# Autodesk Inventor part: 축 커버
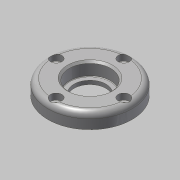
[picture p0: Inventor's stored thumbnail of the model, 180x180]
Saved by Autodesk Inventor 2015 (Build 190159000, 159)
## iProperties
Created: 2015-10
Part Number: 축 커버
Document SubType Name: Modeling
Designer: mdu
Density: 7.86 g/cm^3
Material: 강철, 연강
Mass: 76.1259 g
Surface Area: 48.0703 cm^2
Volume: 9.68523 cm^3
Appearance: Steel
Author: mdu
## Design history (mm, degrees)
sketch "스케치1"
  geometry: C1 r 22.355 at (0, 0) reference; C2 r 14 at (0, 0) reference; C3 r 1.23 at (0, 18) reference; 1 further point
extrude "돌출1" new body sketch "스케치1" distance "d0" = 8; taper "d1" = 0 deg
sketch "스케치2"
  geometry: C1 r 14 at (0, 0) reference; 1 further point
extrude "돌출2" join sketch "스케치2" distance "d2" = 3; taper "d3" = 0 deg
hole "구멍1" diameter "d6" = 17; stored, may be unused: countersink angle "d10" = 90 deg, drill point angle "d12" = 118 deg; dims "d4" = 10, "d5" = 10, "d7" = 6, "d8" = 23, "d9" = 2, "d11" = 8
hole "구멍2" diameter "d15" = 22; stored, may be unused: countersink angle "d19" = 90 deg, drill point angle "d21" = 0 deg; dims "d13" = 10, "d14" = 10, "d16" = 6, "d17" = 25, "d18" = 2, "d20" = 7
fillet "모깎기1" dims "d22" = 3, "d23" = 0.3
chamfer "모따기1" distance "d24" = 1; stored, may be unused: second distance "d25" = 2, angle "d26" = 45 deg
sketch "스케치3"
  geometry: 2 further points
hole "구멍3" sketch "스케치3" at (0, 18) diameter "d27" = 3.4; stored, may be unused: countersink angle "d31" = 90 deg, drill point angle "d33" = 118 deg; dims "d28" = 6, "d29" = 6, "d30" = 3.3, "d32" = 7
node "솔리드1"
pattern_circular "원형 패턴1" dims angle "d35" = 360 deg
node "참조1"
node "참조2"
node "참조3"
